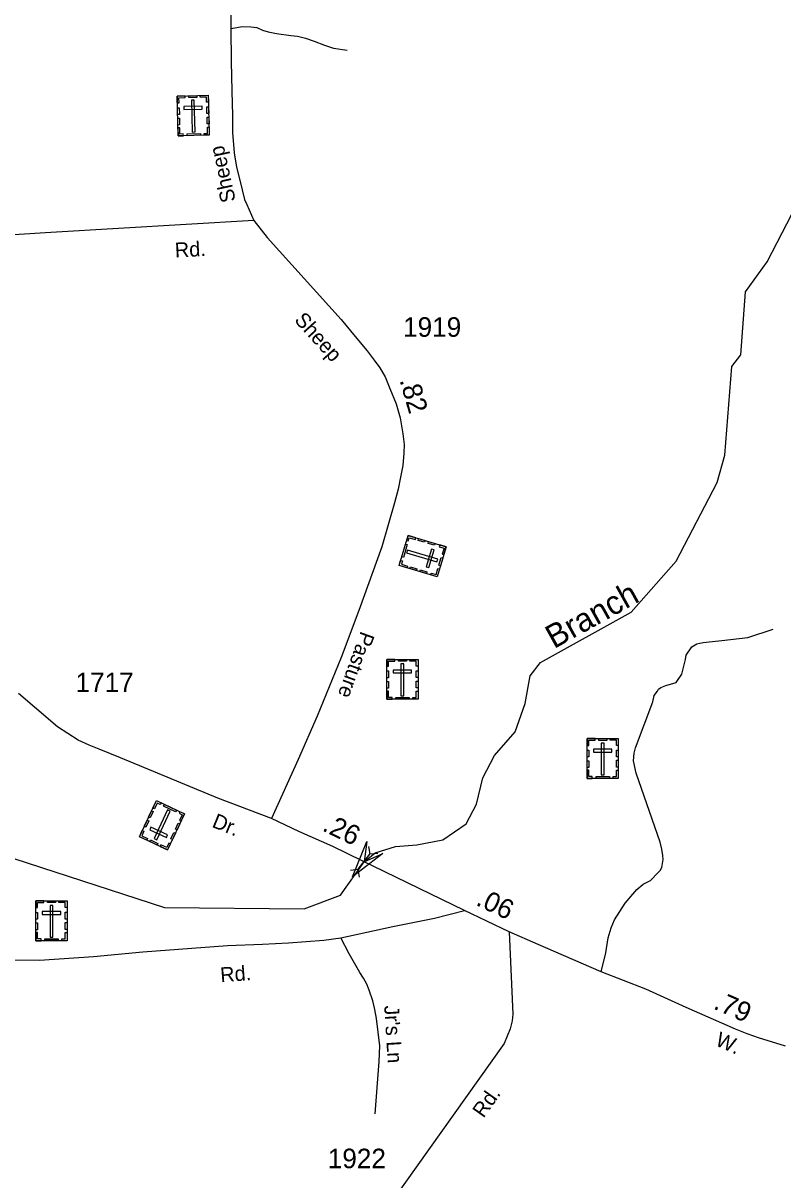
# Model space of a CAD drawing. Extents: x 2220236 to 2384410, y 720751 to 894131.
# Drawn here: x 2280524 to 2285379, y 780491 to 787885 of the extents above; entities that cross this region are included whole.
import ezdxf

# ---------------------------------------------------------------- set-up
doc = ezdxf.new("R2010")
doc.units = 0
for name, color, linetype in [('Exist Cultural Cemetery CELL', 7, 'Continuous'), ('Exist Hydrographic Creek Single Shore', 7, 'Continuous'), ('Exist Hydrographic Creek Single Shore Label', 7, 'Continuous'), ('Exist Road Non-System Type 51', 7, 'Continuous'), ('Exist Road Non-System Type 51 Label', 7, 'Continuous'), ('Exist Road Secondary Mileage Hundredths English Label', 7, 'Continuous'), ('Exist Road Secondary Structure Pipe Attributed CELL', 7, 'Continuous'), ('Exist Road Secondary Structure Pipe CELL', 7, 'Continuous'), ('Exist Road Secondary Type 51 Attributed', 7, 'Continuous'), ('Exist Road Secondary Type 51 Label', 7, 'Continuous'), ('Exist Road Secondary Type 51 Number Label', 7, 'Continuous')]:
    doc.layers.add(name, color=color, linetype=linetype)

msp = doc.modelspace()

# ---------------------------------------------------------------- linework, layer by layer
at = {"layer": 'Exist Cultural Cemetery CELL'}
for points in [[(2281507.9, 787418.3), (2281706.9, 787423.7), (2281713.7, 787169.1), (2281514.7, 787163.8)], [(2281509, 787375), (2281520.4, 787375.3), (2281519.5, 787407.5), (2281560.1, 787408.6), (2281559.8, 787419.7), (2281507.9, 787418.3)], [(2281581.9, 787420.3), (2281633.7, 787421.7), (2281634, 787410.3), (2281582.2, 787408.9)], [(2281617.6, 787392), (2281599, 787391.5), (2281604.4, 787188.7), (2281623.1, 787189.3)], [(2281708.1, 787380.3), (2281696.8, 787380), (2281695.9, 787412.2), (2281655.4, 787411.1), (2281655.1, 787422.2), (2281706.9, 787423.6)], [(2281511, 787300.9), (2281509.8, 787344.2), (2281521.2, 787344.5), (2281522.4, 787301.2)], [(2281550.5, 787351.4), (2281551, 787332.7), (2281668.7, 787335.9), (2281668.2, 787354.6)], [(2281698.7, 787307), (2281697.5, 787350.3), (2281708.9, 787350.6), (2281710.1, 787307.3)], [(2281512.8, 787233.7), (2281511.6, 787277), (2281523, 787277.3), (2281524.2, 787234)], [(2281700.4, 787241.1), (2281699.3, 787284.4), (2281710.6, 787284.7), (2281711.8, 787241.4)], [(2281547.8, 787164.7), (2281547.5, 787176.2), (2281525.5, 787175.6), (2281524.4, 787216), (2281513.3, 787215.7), (2281514.7, 787163.8)], [(2281571.8, 787176.8), (2281656.7, 787179.1), (2281657, 787167.7), (2281572.1, 787165.4)], [(2281680.6, 787168.2), (2281680.3, 787179.7), (2281702.3, 787180.3), (2281701.2, 787220.7), (2281712.3, 787221), (2281713.7, 787169.1)], [(2283227.7, 784536.8), (2283170.8, 784346), (2282926.8, 784418.8), (2282983.7, 784609.6)], [(2282974.3, 784577.9), (2282985.3, 784574.6), (2282991.6, 784595.7), (2283030.3, 784584.1), (2283033.5, 784594.8), (2282983.8, 784609.6)], [(2283050.8, 784589.6), (2283092.3, 784577.2), (2283089, 784566.3), (2283047.5, 784578.7)], [(2282978.3, 784551.2), (2282954.1, 784469.9), (2282943.1, 784473.2), (2282967.4, 784554.5)], [(2283168.5, 784440.7), (2283173.8, 784458.6), (2282979.5, 784516.5), (2282974.2, 784498.6)], [(2283150.9, 784517.1), (2283133, 784522.5), (2283099.3, 784409.6), (2283117.2, 784404.3)], [(2283115.2, 784570.4), (2283156.7, 784558), (2283153.4, 784547.1), (2283111.9, 784559.5)], [(2283186.2, 784549.2), (2283183, 784538.3), (2283213.8, 784529.1), (2283202.2, 784490.2), (2283212.9, 784487.1), (2283227.7, 784536.8)], [(2282936.3, 784450.5), (2282947.3, 784447.2), (2282941, 784426.2), (2282979.7, 784414.6), (2282976.6, 784403.9), (2282926.8, 784418.8)], [(2283206.5, 784465.8), (2283191.7, 784416.2), (2283180.8, 784419.4), (2283195.6, 784469.1)], [(2282999.3, 784409), (2283040.8, 784396.6), (2283037.6, 784385.7), (2282996.1, 784398.1)], [(2283062.5, 784390.2), (2283104, 784377.8), (2283100.8, 784366.9), (2283059.2, 784379.2)], [(2283129.3, 784358.3), (2283132.5, 784369.2), (2283163.4, 784360), (2283174.9, 784398.9), (2283185.6, 784395.7), (2283170.8, 784346)], [(2282848.2, 783817.9), (2283047.3, 783817.9), (2283047.3, 783563.2), (2282848.2, 783563.2)], [(2282848.2, 783774.5), (2282859.5, 783774.5), (2282859.5, 783806.7), (2282900.1, 783806.7), (2282900.1, 783817.9), (2282848.2, 783817.9)], [(2282922.3, 783817.8), (2282974.1, 783817.8), (2282974.1, 783806.4), (2282922.3, 783806.4)], [(2282957.2, 783788.6), (2282938.5, 783788.6), (2282938.5, 783585.8), (2282957.2, 783585.8)], [(2283047.3, 783774.5), (2283036, 783774.5), (2283036, 783806.7), (2282995.4, 783806.7), (2282995.4, 783817.8), (2283047.3, 783817.8)], [(2282848.2, 783700.4), (2282848.2, 783743.7), (2282859.6, 783743.7), (2282859.6, 783700.4)], [(2282889, 783749.8), (2282889, 783731.1), (2283006.7, 783731.1), (2283006.7, 783749.8)], [(2283035.9, 783701.4), (2283035.9, 783744.7), (2283047.3, 783744.7), (2283047.3, 783701.4)], [(2282848.2, 783633.2), (2282848.2, 783676.5), (2282859.5, 783676.5), (2282859.5, 783633.2)], [(2283035.9, 783635.5), (2283035.9, 783678.8), (2283047.3, 783678.8), (2283047.3, 783635.5)], [(2282881.3, 783563.3), (2282881.3, 783574.8), (2282859.3, 783574.8), (2282859.3, 783615.2), (2282848.1, 783615.2), (2282848.1, 783563.3)], [(2282905.6, 783574.7), (2282990.5, 783574.7), (2282990.5, 783563.3), (2282905.6, 783563.3)], [(2283014.1, 783563.2), (2283014.1, 783574.7), (2283036.1, 783574.7), (2283036.1, 783615.1), (2283047.3, 783615.1), (2283047.3, 783563.2)], [(2284128.1, 783311.7), (2284327.2, 783311.7), (2284327.2, 783057.1), (2284128.1, 783057.1)], [(2284128.1, 783268.4), (2284139.4, 783268.4), (2284139.4, 783300.6), (2284180, 783300.6), (2284180, 783311.7), (2284128.1, 783311.7)], [(2284202.2, 783311.7), (2284254, 783311.7), (2284254, 783300.3), (2284202.2, 783300.3)], [(2284237.1, 783282.4), (2284218.4, 783282.4), (2284218.4, 783079.6), (2284237.1, 783079.6)], [(2284327.3, 783268.4), (2284315.9, 783268.4), (2284315.9, 783300.6), (2284275.3, 783300.5), (2284275.3, 783311.7), (2284327.2, 783311.7)], [(2284128.1, 783194.3), (2284128.1, 783237.6), (2284139.5, 783237.6), (2284139.5, 783194.3)], [(2284168.9, 783243.7), (2284168.9, 783225), (2284286.7, 783225), (2284286.7, 783243.7)], [(2284315.8, 783195.3), (2284315.8, 783238.6), (2284327.2, 783238.6), (2284327.2, 783195.3)], [(2284161.2, 783057.1), (2284161.2, 783068.6), (2284139.2, 783068.6), (2284139.2, 783109), (2284128, 783109), (2284128, 783057.1)], [(2284128.1, 783127), (2284128.1, 783170.4), (2284139.4, 783170.4), (2284139.4, 783127)], [(2284294.1, 783057.1), (2284294.1, 783068.6), (2284316.1, 783068.6), (2284316.1, 783109), (2284327.2, 783109), (2284327.2, 783057.1)], [(2284315.8, 783129.4), (2284315.8, 783172.7), (2284327.2, 783172.7), (2284327.2, 783129.4)], [(2284185.6, 783068.6), (2284270.4, 783068.6), (2284270.4, 783057.2), (2284185.6, 783057.2)], [(2281447, 782599.7), (2281266.9, 782684.5), (2281375.3, 782914.9), (2281555.5, 782830.1)], [(2281405.3, 782900.8), (2281400.4, 782890.4), (2281380.5, 782899.7), (2281363.3, 782863.2), (2281353.2, 782867.9), (2281375.3, 782914.9)], [(2281498.6, 782844.2), (2281421.8, 782880.3), (2281426.7, 782890.6), (2281503.4, 782854.5)], [(2281354.8, 782844.6), (2281336.4, 782805.5), (2281326.1, 782810.3), (2281344.5, 782849.5)], [(2281360.9, 782672.6), (2281377.8, 782664.7), (2281464.1, 782848.2), (2281447.2, 782856.1)], [(2281525.5, 782844.2), (2281520.6, 782833.8), (2281540.5, 782824.4), (2281523.3, 782787.8), (2281533.4, 782783.1), (2281555.5, 782830)], [(2281326.7, 782785), (2281308.3, 782745.8), (2281298, 782750.7), (2281316.4, 782789.9)], [(2281439.1, 782678.7), (2281447, 782695.6), (2281340.5, 782745.7), (2281332.6, 782728.8)], [(2281525.7, 782766.8), (2281507.3, 782727.6), (2281497, 782732.5), (2281515.4, 782771.7)], [(2281285.3, 782723.7), (2281295.6, 782718.9), (2281281.9, 782689.8), (2281318.6, 782672.5), (2281313.8, 782662.5), (2281266.9, 782684.5)], [(2281380, 782631.3), (2281333.1, 782653.3), (2281338, 782663.6), (2281384.9, 782641.6)], [(2281497.1, 782706), (2281478.6, 782666.8), (2281468.3, 782671.7), (2281486.8, 782710.8)], [(2281465.5, 782638.9), (2281455.2, 782643.7), (2281441.5, 782614.6), (2281404.8, 782631.9), (2281400.1, 782621.8), (2281447, 782599.7)], [(2280605.4, 782274.4), (2280804.5, 782274.4), (2280804.5, 782019.8), (2280605.4, 782019.8)], [(2280605.4, 782231.1), (2280616.7, 782231.1), (2280616.7, 782263.3), (2280657.3, 782263.3), (2280657.3, 782274.4), (2280605.4, 782274.4)], [(2280679.4, 782274.4), (2280731.3, 782274.4), (2280731.3, 782263), (2280679.4, 782263)], [(2280714.4, 782245.1), (2280695.7, 782245.1), (2280695.7, 782042.3), (2280714.4, 782042.3)], [(2280804.5, 782231.1), (2280793.2, 782231.1), (2280793.2, 782263.2), (2280752.6, 782263.2), (2280752.6, 782274.4), (2280804.5, 782274.4)], [(2280605.4, 782156.9), (2280605.4, 782200.3), (2280616.7, 782200.3), (2280616.7, 782156.9)], [(2280646.2, 782206.4), (2280646.2, 782187.7), (2280763.9, 782187.7), (2280763.9, 782206.4)], [(2280793.1, 782158), (2280793.1, 782201.3), (2280804.5, 782201.3), (2280804.5, 782158)], [(2280605.3, 782089.7), (2280605.3, 782133), (2280616.7, 782133), (2280616.7, 782089.7)], [(2280638.5, 782019.8), (2280638.5, 782031.3), (2280616.5, 782031.3), (2280616.5, 782071.7), (2280605.3, 782071.7), (2280605.3, 782019.8)], [(2280771.3, 782019.8), (2280771.3, 782031.3), (2280793.3, 782031.3), (2280793.3, 782071.7), (2280804.5, 782071.7), (2280804.5, 782019.8)], [(2280793.1, 782092.1), (2280793.1, 782135.4), (2280804.5, 782135.4), (2280804.5, 782092.1)], [(2280662.8, 782031.3), (2280747.7, 782031.3), (2280747.7, 782019.9), (2280662.8, 782019.9)]]:
    msp.add_lwpolyline(points, close=True, dxfattribs=at)
at = {"layer": 'Exist Hydrographic Creek Single Shore'}
msp.add_lwpolyline([(2280108.1, 782660), (2281428, 782232.7), (2282319.2, 782224.2), (2282552.1, 782311.2), (2282702.9, 782524.3), (2282772.7, 782580.4), (2282904, 782621.8), (2283040.1, 782632.4), (2283207, 782665), (2283356.1, 782766.9), (2283421.1, 782893.4), (2283461.1, 783059.9), (2283535.1, 783202.7), (2283667.2, 783354.1), (2283731.2, 783536.5), (2283763.2, 783712.9), (2283829.2, 783796.9), (2284409.1, 784119.4), (2284697.2, 784444.7), (2284959, 784947.7), (2285008, 785123.8), (2285052.1, 785690.3), (2285110.2, 785764.5), (2285139.1, 786167.3), (2285279.1, 786358), (2285500.2, 786786.3)], dxfattribs=at)
at = {"layer": 'Exist Road Non-System Type 51'}
for points in [[(2281850.7, 787851.3), (2281926.5, 787863.7), (2281978.4, 787862.2), (2282016.5, 787856.4), (2282052.6, 787840.9), (2282090.7, 787829.3), (2282142.9, 787817.6), (2282234.8, 787806.5), (2282278.2, 787801.2), (2282327.8, 787789.3), (2282383.4, 787769.4), (2282450.8, 787743.6), (2282506.4, 787725.7), (2282595.6, 787711.8)], [(2284218.4, 781820.9), (2284246.9, 781942.2), (2284262.1, 782038.3), (2284281.5, 782102.5), (2284303.1, 782152.6), (2284372.1, 782259.2), (2284445.1, 782347.8), (2284486.7, 782380.3), (2284532.6, 782404.6), (2284580, 782453.2), (2284593.9, 782469.3), (2284605.7, 782487.3), (2284613.2, 782539.3), (2284610.9, 782565.3), (2284604.5, 782605.2), (2284594.3, 782649), (2284440.5, 783091), (2284423.9, 783168.9), (2284428, 783218.3), (2284437.2, 783252.1), (2284547.6, 783546.7), (2284556.8, 783586.6), (2284578.3, 783614.2), (2284585.1, 783628.5), (2284599.8, 783638.8), (2284630, 783651.7), (2284697.9, 783669.5), (2284734.1, 783722.4), (2284755.9, 783816.1), (2284760.6, 783845.8), (2284798, 783897.3), (2284829.9, 783918.1), (2284848.3, 783921.1), (2284870.3, 783926.3), (2284888.3, 783928.3), (2284989.4, 783939.6), (2285155, 783958), (2285317.6, 784010.2)], [(2282773.3, 780912.8), (2282800.2, 781246.9), (2282803.3, 781346.9), (2282781.7, 781522.7), (2282771.1, 781580.5), (2282758.7, 781636.3), (2282736.1, 781704.1), (2282719.7, 781741.9), (2282699.3, 781779.7), (2282675, 781815.6), (2282607.9, 781936.7), (2282554.9, 782038.2)]]:
    msp.add_lwpolyline(points, dxfattribs=at)
at = {"layer": 'Exist Road Secondary Structure Pipe Attributed CELL'}
msp.add_lwpolyline([(2282821.6, 782577.2), (2282629.6, 782426.9), (2282720.7, 782653.1), (2282702.9, 782524.3)], close=True, dxfattribs=at)
at = {"layer": 'Exist Road Secondary Structure Pipe CELL'}
for p, q in [((2282731.9, 782622.4), (2282739.8, 782572.2)), ((2282665.9, 782476.5), (2282739.8, 782572.2)), ((2282790.3, 782577.3), (2282739.8, 782572.2)), ((2282615.4, 782471.3), (2282665.9, 782476.5)), ((2282673.8, 782426.3), (2282665.9, 782476.5))]:
    msp.add_line(p, q, dxfattribs=at)
at = {"layer": 'Exist Road Secondary Type 51 Attributed'}
msp.add_line((2283629.2, 782077), (2283345.5, 782212), dxfattribs=at)
for points in [[(2282200.6, 789401.9), (2282148.3, 789265.7), (2282070.9, 789051.3), (2281990.5, 788831), (2281945.9, 788697), (2281925.1, 788604.6), (2281910.2, 788548.1), (2281889.4, 788458.7), (2281877.5, 788390.3), (2281862.6, 788321.8), (2281851.2, 787997.9), (2281850.7, 787851.3), (2281853.7, 787639.9), (2281856.6, 787449.3), (2281862.6, 787294.5), (2281861.6, 787185.8), (2281873.5, 787056.7), (2281887.4, 786963.4), (2281909.2, 786880.1), (2281939, 786758), (2281952.8, 786726.2), (2281998.5, 786624)], [(2281998.5, 786624), (2280701, 786546.5), (2280464.9, 786532.7), (2280334, 786526.7), (2280207, 786495.9), (2280095.9, 786468.1), (2280012.6, 786440.3), (2279702.4, 786289.5), (2279594.9, 786240.6), (2279483.5, 786181.5), (2279380, 786136.4), (2279248.2, 786099.4), (2279148.6, 786076.4), (2279014.8, 786055.2), (2278946.8, 786054.4), (2278882.9, 786057.9), (2278536.7, 786102.7), (2278264.5, 786136.1), (2277668.1, 786214.4), (2277533.8, 786226.2)], [(2281998.5, 786624), (2282083.8, 786513.8), (2282555.9, 785989.7), (2282645.2, 785882.5), (2282722.6, 785789.2), (2282768.2, 785729.7), (2282803.9, 785682), (2282837.7, 785624.4), (2282867.4, 785549), (2282907.1, 785451.7), (2282932.9, 785362.4), (2282950.7, 785259.2), (2282958.7, 785191.7), (2282956.7, 785136.1), (2282950.7, 785057.7), (2282934.9, 784982.3), (2282921, 784906.8), (2282897.2, 784817.5), (2282815.8, 784537.6), (2282669, 784130.6), (2282555.9, 783829.9), (2282403.2, 783454.7), (2282282.2, 783178.7), (2282111.6, 782801.6)], [(2282111.6, 782801.6), (2281768.4, 782929.8), (2281145.7, 783187.6), (2281010.7, 783242.9), (2280946.3, 783270.5), (2280875.8, 783301.2), (2280743.9, 783387.1), (2280596.6, 783513), (2280495.4, 783598.9)], [(2283345.5, 782212), (2282690.9, 782529.6), (2282502.4, 782620.9), (2282286.1, 782718.2), (2282111.6, 782801.6)], [(2280435.4, 781896.5), (2280629.1, 781896.2), (2280972.9, 781919.3), (2281288.4, 781948.4), (2281829.7, 781989.4), (2282053.6, 781997.6), (2282218.7, 782006.5), (2282331.8, 782014.5), (2282445.2, 782023.3), (2282554.9, 782038.2), (2282887.3, 782110.7), (2283153.1, 782164.3), (2283345.5, 782212)], [(2283629.2, 782077), (2283653, 781549.9), (2283649.1, 781508.2), (2283637.2, 781456.6), (2283597.5, 781363.3), (2281685, 778673.5)], [(2285396.1, 781345.3), (2285223.6, 781399.6), (2285151.4, 781424.9), (2285075.2, 781454.3), (2284760.2, 781593.1), (2284503.1, 781710.8), (2284218.4, 781820.9), (2283976.4, 781924.1), (2283815.7, 781995.6), (2283629.2, 782077)]]:
    msp.add_lwpolyline(points, dxfattribs=at)

# ---------------------------------------------------------------- texts
at = {"layer": 'Exist Hydrographic Creek Single Shore Label'}
msp.add_text('Branch', height=150, rotation=29.08418, dxfattribs=at).set_placement((2283916.1, 783882.7))
at = {"layer": 'Exist Road Non-System Type 51 Label'}
msp.add_text("Jr's Ln", height=95, rotation=273.61171, dxfattribs=at).set_placement((2282830.9, 781603.7))
at = {"layer": 'Exist Road Secondary Mileage Hundredths English Label'}
for s, rotation, p in [('.82', 286.1032, (2282928.5, 785602.9)), ('.26', 334.14888, (2282429.4, 782725.7)), ('.06', 334.5533, (2283411.2, 782249.9)), ('.79', 336.21966, (2284929.1, 781587))]:
    msp.add_text(s, height=125, rotation=rotation, dxfattribs=at).set_placement(p)
at = {"layer": 'Exist Road Secondary Type 51 Label'}
for s, rotation, p in [('Sheep', 102.25054, (2281882.8, 786749.5)), ('Rd.', 2.90846, (2281495.7, 786386.5)), ('Sheep', 312.15471, (2282252.5, 785983.8)), ('Pasture', 250.08795, (2282683, 784002.8)), ('Dr.', 338.04143, (2281725.2, 782748.2)), ('Rd.', 4.33157, (2281787, 781753.6)), ('W.', 336.21966, (2284940.8, 781353.3)), ('Rd.', 54.64024, (2283465.8, 780881.3))]:
    msp.add_text(s, height=95, rotation=rotation, dxfattribs=at).set_placement(p)
at = {"layer": 'Exist Road Secondary Type 51 Number Label'}
for s, p in [('1919', (2282951.8, 785879.9)), ('1717', (2280858.7, 783608.3)), ('1922', (2282470.5, 780565.2))]:
    msp.add_text(s, height=125, dxfattribs=at).set_placement(p)

doc.saveas('drawing.dxf')
